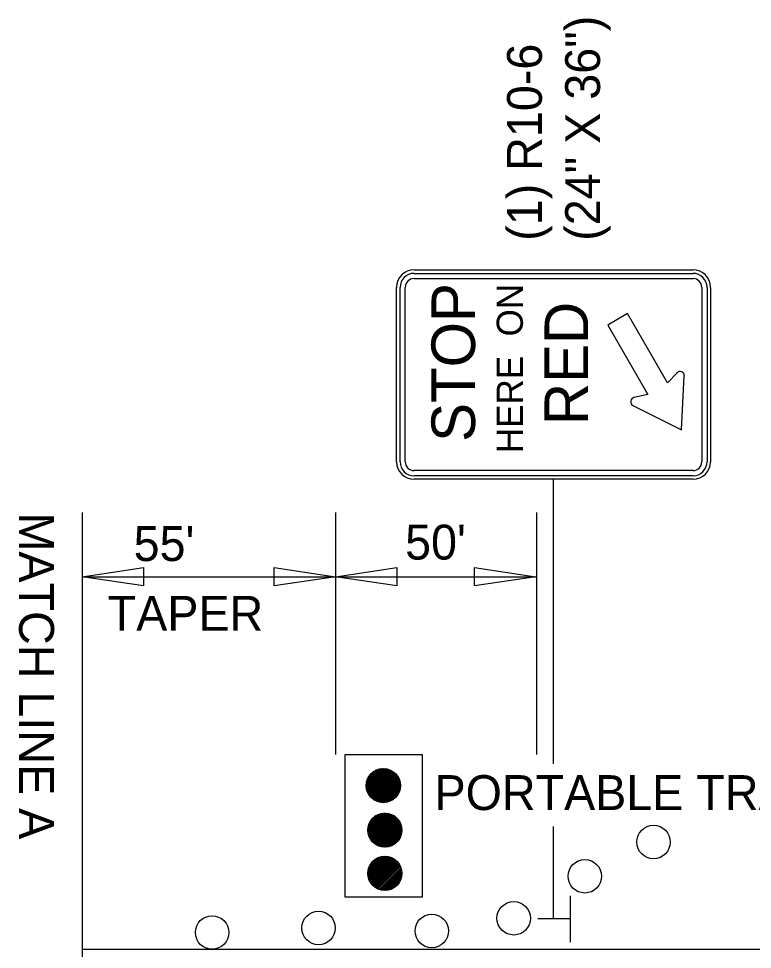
# Model space of a CAD drawing. Extents: x 1930579 to 1939784, y 596179 to 597522.
# Drawn here: x 1937433.7 to 1937559.9, y 596502.4 to 596662.4 of the extents above; entities that cross this region are included whole.
import ezdxf

# ---------------------------------------------------------------- set-up
doc = ezdxf.new("R2010")
doc.units = 0
for name, color, linetype in [('Default', 7, 'Continuous'), ('P_TC_Signs_Permanent', 7, 'Continuous'), ('R_Annotation', 7, 'Continuous')]:
    doc.layers.add(name, color=color, linetype=linetype)

msp = doc.modelspace()

# ---------------------------------------------------------------- linework, layer by layer
at = {"layer": 'Default'}
for p, q in [((1937444.6, 596577.52), (1937444.6, 596466.89)), ((1937488.16, 596577.52), (1937488.16, 596535.94)), ((1937522.73, 596577.52), (1937522.73, 596535.94)), ((1937444.6, 596566.48), (1937455.15, 596568.06)), ((1937455.15, 596568.06), (1937455.15, 596564.9)), ((1937477.62, 596564.9), (1937477.62, 596568.06)), ((1937477.62, 596568.06), (1937488.16, 596566.48)), ((1937488.16, 596566.48), (1937498.71, 596568.06)), ((1937498.71, 596568.06), (1937498.71, 596564.9)), ((1937512.07, 596564.9), (1937512.07, 596568.06)), ((1937512.07, 596568.06), (1937522.62, 596566.48)), ((1937455.15, 596564.9), (1937444.6, 596566.48)), ((1937444.6, 596566.48), (1937488.16, 596566.48)), ((1937488.16, 596566.48), (1937477.62, 596564.9)), ((1937488.16, 596566.48), (1937522.62, 596566.48)), ((1937498.71, 596564.9), (1937488.16, 596566.48)), ((1937522.62, 596566.48), (1937512.07, 596564.9)), ((1937493.44, 596530.63), (1937496.33, 596533.53)), ((1937493.44, 596530.45), (1937496.51, 596533.52)), ((1937493.44, 596530.82), (1937496.14, 596533.52)), ((1937493.45, 596530.28), (1937496.68, 596533.51)), ((1937493.47, 596531.02), (1937495.94, 596533.49)), ((1937493.47, 596530.12), (1937496.84, 596533.49)), ((1937493.5, 596529.97), (1937496.99, 596533.46)), ((1937493.51, 596531.24), (1937495.72, 596533.45)), ((1937493.54, 596529.82), (1937497.14, 596533.43)), ((1937493.58, 596529.68), (1937497.28, 596533.38)), ((1937493.58, 596531.49), (1937495.47, 596533.38)), ((1937493.62, 596529.55), (1937497.41, 596533.34)), ((1937493.68, 596529.42), (1937497.54, 596533.29)), ((1937493.69, 596531.79), (1937495.17, 596533.27)), ((1937493.73, 596529.3), (1937497.67, 596533.23)), ((1937493.79, 596529.18), (1937497.78, 596533.17)), ((1937493.86, 596529.06), (1937497.9, 596533.1)), ((1937493.91, 596532.19), (1937494.77, 596533.05)), ((1937493.93, 596528.95), (1937498.01, 596533.03)), ((1937494, 596528.84), (1937498.12, 596532.96)), ((1937494.08, 596528.74), (1937498.22, 596532.88)), ((1937494.17, 596528.64), (1937498.32, 596532.79)), ((1937494.25, 596528.55), (1937498.41, 596532.71)), ((1937494.34, 596528.46), (1937498.5, 596532.62)), ((1937494.44, 596528.37), (1937498.59, 596532.52)), ((1937494.54, 596528.29), (1937498.67, 596532.43)), ((1937494.64, 596528.21), (1937498.75, 596532.32)), ((1937494.74, 596528.14), (1937498.82, 596532.22)), ((1937494.85, 596528.07), (1937498.89, 596532.11)), ((1937494.97, 596528), (1937498.96, 596531.99)), ((1937495.09, 596527.94), (1937499.02, 596531.87)), ((1937495.21, 596527.88), (1937499.08, 596531.75)), ((1937495.34, 596527.83), (1937499.13, 596531.62)), ((1937495.48, 596527.78), (1937499.18, 596531.48)), ((1937495.62, 596527.74), (1937499.22, 596531.34)), ((1937495.76, 596527.71), (1937499.25, 596531.2)), ((1937495.91, 596527.68), (1937499.28, 596531.05)), ((1937496.07, 596527.66), (1937499.3, 596530.89)), ((1937496.24, 596527.65), (1937499.32, 596530.72)), ((1937496.42, 596527.64), (1937499.32, 596530.54)), ((1937496.61, 596527.65), (1937499.31, 596530.35)), ((1937496.82, 596527.67), (1937499.29, 596530.15)), ((1937497.04, 596527.72), (1937499.24, 596529.92)), ((1937497.29, 596527.79), (1937499.17, 596529.67)), ((1937497.58, 596527.9), (1937499.06, 596529.38)), ((1937497.98, 596528.12), (1937498.84, 596528.98)), ((1937493.7, 596522.97), (1937496.6, 596525.87)), ((1937493.71, 596522.79), (1937496.78, 596525.86)), ((1937493.71, 596523.16), (1937496.41, 596525.86)), ((1937493.72, 596522.62), (1937496.95, 596525.85)), ((1937493.74, 596522.46), (1937497.11, 596525.83)), ((1937493.74, 596523.36), (1937496.21, 596525.83)), ((1937493.77, 596522.31), (1937497.26, 596525.8)), ((1937493.78, 596523.58), (1937495.99, 596525.79)), ((1937493.8, 596522.16), (1937497.41, 596525.77)), ((1937493.85, 596522.02), (1937497.55, 596525.72)), ((1937493.85, 596523.83), (1937495.74, 596525.72)), ((1937493.89, 596521.89), (1937497.68, 596525.68)), ((1937493.94, 596521.76), (1937497.81, 596525.63)), ((1937493.96, 596524.13), (1937495.44, 596525.61)), ((1937494, 596521.64), (1937497.93, 596525.57)), ((1937494.06, 596521.52), (1937498.05, 596525.51)), ((1937494.13, 596521.4), (1937498.17, 596525.44)), ((1937494.18, 596524.53), (1937495.04, 596525.39)), ((1937494.2, 596521.29), (1937498.28, 596525.37)), ((1937494.27, 596521.18), (1937498.39, 596525.3)), ((1937494.35, 596521.08), (1937498.49, 596525.22)), ((1937494.44, 596520.98), (1937498.59, 596525.14)), ((1937494.52, 596520.89), (1937498.68, 596525.05)), ((1937494.61, 596520.8), (1937498.77, 596524.96)), ((1937494.71, 596520.71), (1937498.86, 596524.86)), ((1937494.8, 596520.63), (1937498.94, 596524.77)), ((1937494.91, 596520.55), (1937499.02, 596524.66)), ((1937495.01, 596520.48), (1937499.09, 596524.56)), ((1937495.12, 596520.41), (1937499.16, 596524.45)), ((1937495.24, 596520.34), (1937499.23, 596524.33)), ((1937495.36, 596520.28), (1937499.29, 596524.21)), ((1937495.48, 596520.22), (1937499.35, 596524.09)), ((1937495.61, 596520.17), (1937499.4, 596523.96)), ((1937495.75, 596520.12), (1937499.45, 596523.83)), ((1937495.89, 596520.08), (1937499.49, 596523.69)), ((1937496.03, 596520.05), (1937499.52, 596523.54)), ((1937496.18, 596520.02), (1937499.55, 596523.39)), ((1937496.34, 596520), (1937499.57, 596523.23)), ((1937496.51, 596519.99), (1937499.58, 596523.06)), ((1937496.69, 596519.98), (1937499.59, 596522.88)), ((1937496.88, 596519.99), (1937499.58, 596522.69)), ((1937497.08, 596520.02), (1937499.55, 596522.49)), ((1937497.31, 596520.06), (1937499.51, 596522.26)), ((1937497.56, 596520.13), (1937499.44, 596522.01)), ((1937497.85, 596520.24), (1937499.33, 596521.72)), ((1937498.25, 596520.46), (1937499.11, 596521.32)), ((1937493.7, 596515.45), (1937496.68, 596518.43)), ((1937493.71, 596515.27), (1937496.86, 596518.42)), ((1937493.71, 596515.63), (1937496.5, 596518.42)), ((1937493.72, 596515.83), (1937496.3, 596518.41)), ((1937493.73, 596515.11), (1937497.02, 596518.4)), ((1937493.75, 596514.95), (1937497.18, 596518.38)), ((1937493.76, 596516.04), (1937496.09, 596518.37)), ((1937493.78, 596514.8), (1937497.33, 596518.35)), ((1937493.81, 596516.28), (1937495.85, 596518.32)), ((1937493.82, 596514.66), (1937497.47, 596518.31)), ((1937493.87, 596514.52), (1937497.61, 596518.27)), ((1937493.9, 596516.55), (1937495.58, 596518.23)), ((1937493.92, 596514.39), (1937497.74, 596518.22)), ((1937493.97, 596514.27), (1937497.87, 596518.16)), ((1937494.03, 596514.14), (1937497.99, 596518.1)), ((1937494.06, 596516.89), (1937495.24, 596518.07)), ((1937494.09, 596514.03), (1937498.11, 596518.04)), ((1937494.16, 596513.91), (1937498.22, 596517.97)), ((1937494.23, 596513.8), (1937498.33, 596517.9)), ((1937494.31, 596513.7), (1937498.43, 596517.82)), ((1937494.39, 596513.6), (1937498.53, 596517.74)), ((1937494.47, 596513.5), (1937498.63, 596517.66)), ((1937494.56, 596513.41), (1937498.72, 596517.57)), ((1937494.65, 596513.32), (1937498.81, 596517.48)), ((1937494.75, 596513.24), (1937498.89, 596517.38)), ((1937494.85, 596513.16), (1937498.98, 596517.28)), ((1937494.95, 596513.08), (1937499.05, 596517.18)), ((1937495.06, 596513.01), (1937499.12, 596517.07)), ((1937495.17, 596512.94), (1937499.19, 596516.96)), ((1937495.29, 596512.87), (1937499.26, 596516.84)), ((1937495.41, 596512.81), (1937499.32, 596516.72)), ((1937495.67, 596512.71), (1937499.42, 596516.46)), ((1937495.81, 596512.67), (1937499.47, 596516.32)), ((1937495.95, 596512.63), (1937499.5, 596516.18)), ((1937496.1, 596512.6), (1937499.54, 596516.03)), ((1937496.25, 596512.57), (1937499.56, 596515.88)), ((1937496.42, 596512.55), (1937499.58, 596515.71)), ((1937496.59, 596512.54), (1937499.59, 596515.54)), ((1937496.77, 596512.55), (1937499.59, 596515.36)), ((1937496.97, 596512.56), (1937499.57, 596515.16)), ((1937497.18, 596512.59), (1937499.54, 596514.95)), ((1937497.41, 596512.65), (1937499.49, 596514.72)), ((1937497.68, 596512.73), (1937499.4, 596514.45)), ((1937498.01, 596512.88), (1937499.25, 596514.12)), ((1937498.58, 596513.27), (1937498.86, 596513.55)), ((1937528.51, 596511.65), (1937528.51, 596503.64)), ((1937528.39, 596507.67), (1937522.93, 596507.67)), ((1937444.6, 596502.47), (1938059.31, 596502.42))]:
    msp.add_line(p, q, dxfattribs=at)
msp.add_lwpolyline([(1937489.8, 596535.94), (1937503.09, 596535.94), (1937503.09, 596511.4), (1937489.8, 596511.4)], close=True, dxfattribs=at)
for centre, radius in [((1937496.38, 596530.58), 2.94), ((1937496.65, 596522.92), 2.94), ((1937542.86, 596520.87), 2.88), ((1937496.65, 596515.49), 2.94), ((1937531.04, 596514.99), 2.88), ((1937518.81, 596507.77), 2.88), ((1937466.94, 596505.32), 2.88), ((1937485.24, 596506.1), 2.88), ((1937504.72, 596505.59), 2.88)]:
    msp.add_circle(centre, radius, dxfattribs=at)
at = {"layer": 'P_TC_Signs_Permanent'}
for p, q in [((1937501.66, 596619.23), (1937549.66, 596619.23)), ((1937501.66, 596618.63), (1937549.66, 596618.63)), ((1937501.66, 596617.73), (1937549.66, 596617.73)), ((1937498.66, 596586.23), (1937498.66, 596616.23)), ((1937499.26, 596586.23), (1937499.26, 596616.23)), ((1937500.16, 596586.23), (1937500.16, 596616.23)), ((1937551.16, 596616.23), (1937551.16, 596586.23)), ((1937552.06, 596616.23), (1937552.06, 596586.23)), ((1937552.66, 596616.23), (1937552.66, 596586.23)), ((1937549.66, 596584.73), (1937501.66, 596584.73)), ((1937549.66, 596583.83), (1937501.66, 596583.83)), ((1937549.66, 596583.23), (1937501.66, 596583.23))]:
    msp.add_line(p, q, dxfattribs=at)
for points in [[(1937546.91, 596601.53), (1937545.26, 596599.79), (1937538.38, 596611.71), (1937534.97, 596609.74), (1937541.85, 596597.82), (1937539.48, 596597.27)], [(1937539.32, 596595.93), (1937547.64, 596591.73), (1937548.15, 596601)]]:
    msp.add_lwpolyline(points, dxfattribs=at)
for centre, radius, start, end in [((1937501.66, 596616.23), 3, 90, 180), ((1937501.66, 596616.23), 2.4, 90, 180), ((1937549.66, 596616.23), 3, 360, 90), ((1937549.66, 596616.23), 2.4, 360, 90), ((1937501.66, 596616.23), 1.5, 90, 180), ((1937549.66, 596616.23), 1.5, 360, 90), ((1937547.43, 596601.04), 0.72, 356.857, 136.6377), ((1937539.65, 596596.57), 0.72, 103.0349, 243.2286), ((1937501.66, 596586.23), 3, 180, 270), ((1937501.66, 596586.23), 2.4, 180, 270), ((1937501.66, 596586.23), 1.5, 180, 270), ((1937549.66, 596586.23), 3, 270, 360), ((1937549.66, 596586.23), 2.4, 270, 360), ((1937549.66, 596586.23), 1.5, 270, 360)]:
    msp.add_arc(centre, radius, start, end, dxfattribs=at)
at = {"layer": 'R_Annotation'}
for p, q in [((1937525.66, 596534.34), (1937525.66, 596583.23)), ((1937525.66, 596507.67), (1937525.66, 596523.56))]:
    msp.add_line(p, q, dxfattribs=at)

# ---------------------------------------------------------------- texts
at = {"layer": 'Default'}
for s, height, rotation, p in [('MATCH LINE A', 5.9996, 270, (1937433.74, 596577.52)), ("  55' ", 6, 360, (1937448.98, 596569.18)), ("50'", 6, 360, (1937500.13, 596569.43)), ('TAPER', 6, 360, (1937448.98, 596557.18)), ('PORTABLE TRAFFIC SIGNAL SYSTEM', 5.9996, 360, (1937505.19, 596526.37))]:
    msp.add_text(s, height=height, rotation=rotation, dxfattribs=at).set_placement(p)
at = {"layer": 'P_TC_Signs_Permanent'}
for s, height, p in [('STOP', 7.5, (1937512.16, 596589.66)), ('HERE  ON', 4.5, (1937520.38, 596587.73)), ('RED', 7.5, (1937531.6, 596592.56))]:
    msp.add_text(s, height=height, rotation=90, dxfattribs=at).set_placement(p)
at = {"layer": 'R_Annotation'}
for s, height, p in [('(24" X 36")', 5.9996, (1937533.66, 596624.23)), ('(1) R10-6', 6, (1937523.66, 596624.23))]:
    msp.add_text(s, height=height, rotation=90, dxfattribs=at).set_placement(p)

doc.saveas('drawing.dxf')
